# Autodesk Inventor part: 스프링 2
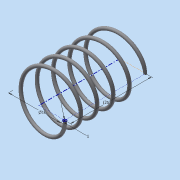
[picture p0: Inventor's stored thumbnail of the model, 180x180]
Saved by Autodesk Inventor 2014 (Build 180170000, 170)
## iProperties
Created: 2015-06
Part Number: 스프링 2
Material: 강철, 연강
Document SubType Name: Modeling
Designer: Administrator
Density: 7.86 g/cm^3
Appearance: 강철
Mass: 1.5292 g
Surface Area: 7.8715 cm^2
Volume: 0.194555 cm^3
Author: Administrator
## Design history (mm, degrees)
sketch "스케치1"
  geometry: L1 (0, 0)-(8, 0); L2 (8, 0)-(8, 14.5); L3 (8, 14.5)-(0, 14.5); L4 (0, 14.5)-(0, 0); C1 r 0.5 at (8, 0)
  constraints: 8 end point, 2 parallel, 1 centre point, 1 coincident, 1 horizontal, 1 perpendicular
  dimensions: "d0" = 1 diameter of C1; "d1" = 16 diameter of L2 L4; "d2" = 14.5 distance of L1.end L2.end (derived)
feature "코일1" pitch "d3" = 10; turns "d5" = 5; dims "d4" = 14.5 (= d2), "d6" = 0, angle "d7" = 90 deg, angle "d8" = 90 deg, "d9" = 0, "d10" = 0
sketch "스케치2"
  geometry: L1 (-8.5, 0)-(-7.5, 0) reference; L2 (-8.5, 0)-(-7.5, 0) reference; 1 further point
  constraints: 2 horizontal alignment
extrude "돌출1" cut sketch "스케치2" stored distance "d11" = 10; taper "d12" = 0 deg
node "작업 평면1"
sketch "스케치3"
  geometry: L1 (8.5, 0)-(7.5, 0) reference; 1 further point
  constraints: 1 horizontal alignment
extrude "돌출2" cut sketch "스케치3" stored distance "d14" = 10; taper "d15" = 0 deg
node "솔리드1"
node "절단 모서리 투영1"
node "절단 모서리 투영2"
node "절단 모서리 투영3"
other parameters: "d13" = -14.5 (= -d2)
